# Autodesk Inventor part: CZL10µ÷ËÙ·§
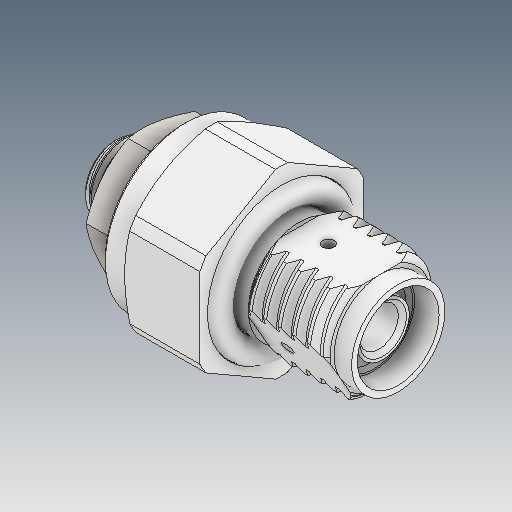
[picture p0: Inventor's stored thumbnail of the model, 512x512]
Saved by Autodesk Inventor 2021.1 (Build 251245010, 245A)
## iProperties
Created: 2021-05
Part Number: CZL10µ÷ËÙ·§
Material: Ogólny
Document SubType Name: Modeling
Designer: user
Density: 1 g/cm^3
Appearance: Domyślna
Author: user
Revision Number: ÈÎºÎ
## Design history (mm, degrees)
feature "ÊäÈë1"
feature "ÊäÈë2"
feature "ÊäÈë5"
node "Bryła1"
node "Bryła2"
node "Bryła3"
